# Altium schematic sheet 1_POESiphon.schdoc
size 309 x 223 mm; Symbol: Sheet-Symbol_A4; Device: Sheet-Symbol_A4; @Project Name: ODrive Rev Motor Module; @Page Count: 5; @Update Date: 2024-10-22; @Create Date: 2024-10-18; @Schematic Name: Schematic-A; @Page No: 1; @Page Name: POESiphon; Company: EasyEDA.com; Reviewed: EasyEDA; Version: V0.1; Page Size: A4; Part Number: JLCPCB-002; Drawn: EasyEDA; @Board Name: BaseModule; @Create Time: 18:23:50; @Update Time: 18:48:05
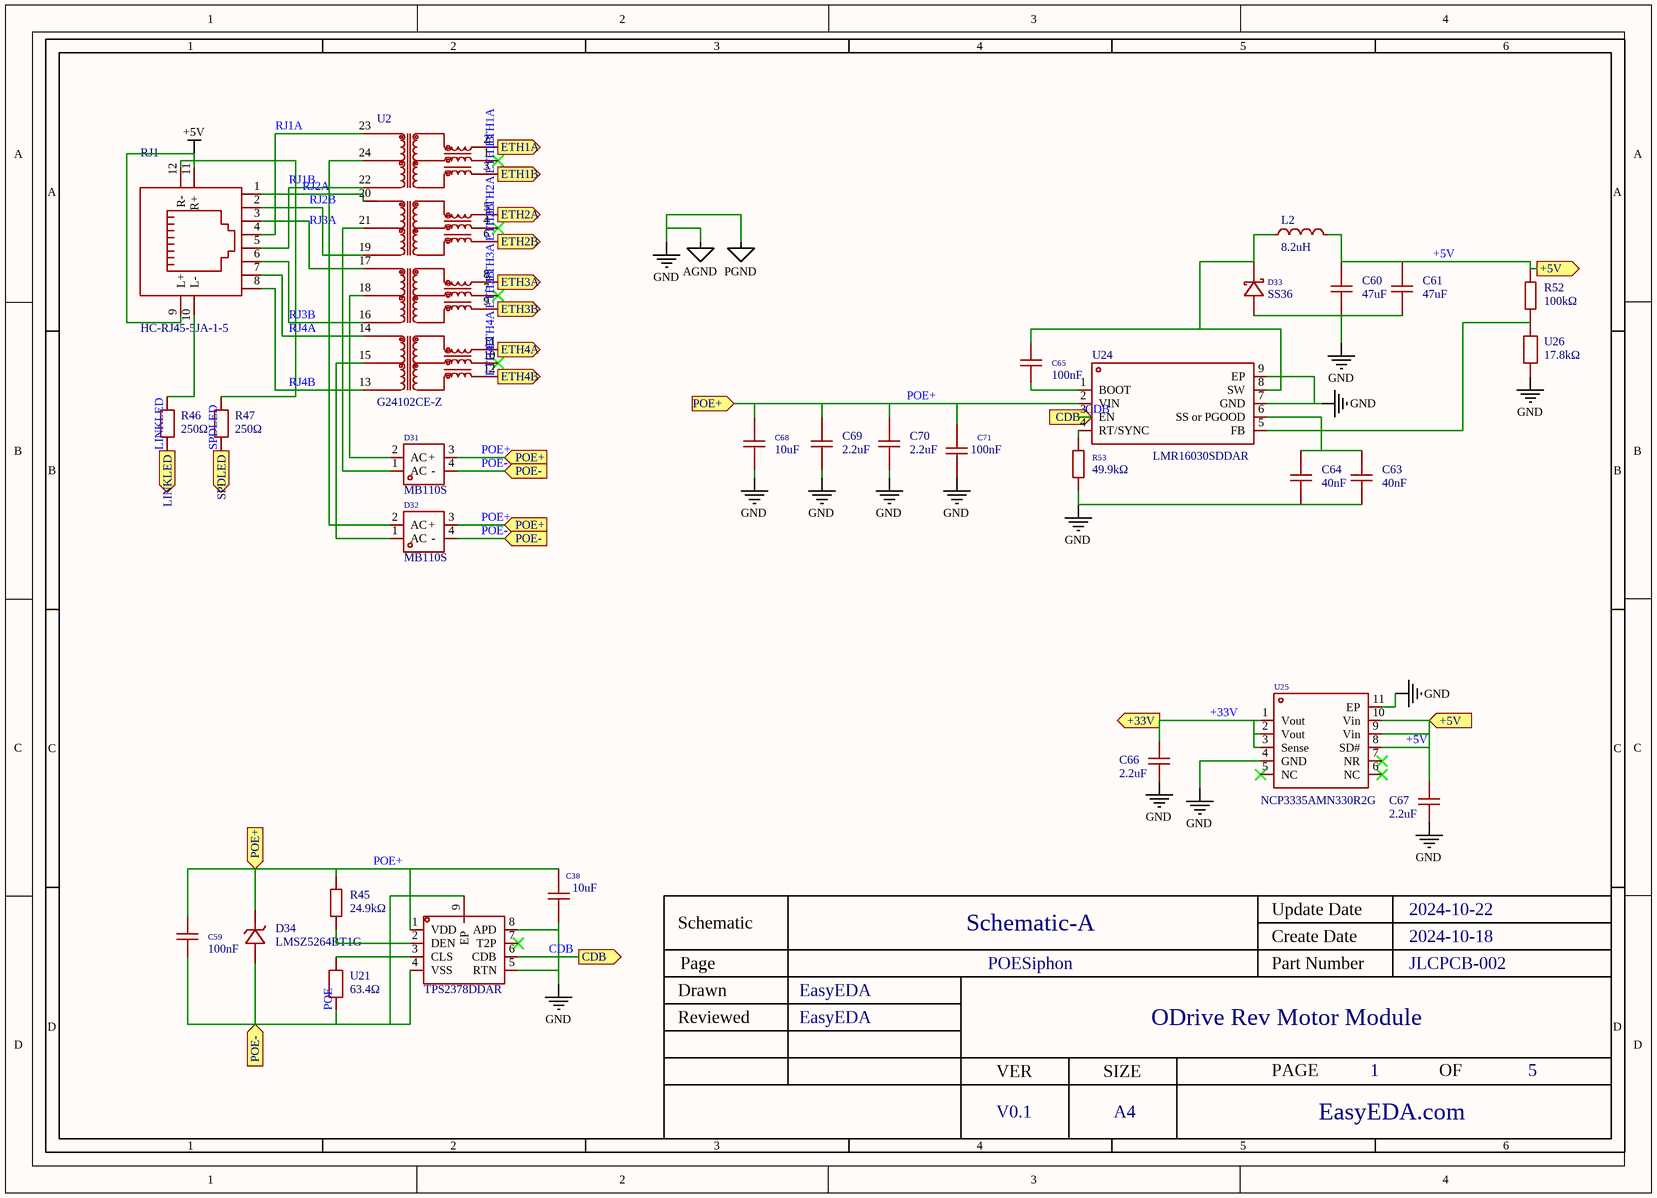
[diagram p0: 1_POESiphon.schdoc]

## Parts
C38  10uF  [C2220]  (value not drawn)
C59  100nF  [C0805]  (value not drawn)
C60  47uF  [C1210]  (value not drawn)
C61  47uF  [C1210]  (value not drawn)
C63  40nF  [C0805]  (value not drawn)
C64  40nF  [C0805]  (value not drawn)
C65  100nF  [C0805]  (value not drawn)
C66  2.2uF  [C0603]  (value not drawn)
C67  2.2uF  [C0603]  (value not drawn)
C68  10uF  [C1210]  (value not drawn)
C69  2.2uF  [C1206]  (value not drawn)
C70  2.2uF  [C1206]  (value not drawn)
C71  100nF  [C0603]  (value not drawn)
D31  MB110S  [MBS_L4.7-W4.0-P2.50-LS7.0-BL]  (value not drawn)
D32  MB110S  [MBS_L4.7-W4.0-P2.50-LS7.0-BL]  (value not drawn)
D33  SS36  [SMA_L4.4-W2.6-LS5.0-RD]  (value not drawn)
D34  LMSZ5264BT1G  [SOD-123_L2.7-W1.6-LS3.7-RD-1]  (value not drawn)
L2  8.2uH  [IND-SMD_L7.0-W6.6_FXL0630]  (value not drawn)
R45  24.9kΩ  [R0603]  (value not drawn)
R46  250Ω  [R0805]  (value not drawn)
R47  250Ω  [R0805]  (value not drawn)
R52  100kΩ  [R0402]  (value not drawn)
R53  49.9kΩ  [R0603]  (value not drawn)
RJ1  HC-RJ45-5JA-1-5  [RJ45-TH_HC-RJ45-5JA-1-5]  (value not drawn)
U2  G24102CE-Z  [SMD-24_L18.2-W12.2-P1.27_G24102CE-Z]  (value not drawn)
U17  TPS2378DDAR  [SO-8_L4.9-W3.9-P1.27-LS6.0-BL-EP]  (value not drawn)
U21  63.4Ω  [R0805]  (value not drawn)
U24  LMR16030SDDAR  [SO-8_L4.9-W3.9-P1.27-LS6.0-BL-EP]  (value not drawn)
U25  NCP3335AMN330R2G  [DFN-10_L3.0-W3.0-P0.50-BL-EP-1]  (value not drawn)
U26  17.8kΩ  [R0603]  (value not drawn)

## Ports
+5V (in), +5V (out), +33V (out), CDB (in), CDB (out), ETH1A (out), ETH1B (out), ETH2A (out), ETH2B (out), ETH3A (out), ETH3B (out), ETH4A (out), ETH4B (out), LINKLED (out), POE+ (in), POE- (in), SPDLED (out)

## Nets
+5V: C60.2 C61.2 C67.2 L2.2 R52.2 RJ1.9(L+) RJ1.11(R+) U25.8(SD#) U25.9(Vin) U25.10(Vin) ; port +5V
AGND: C38.1 C60.1 C61.1 C63.1 C64.1 C66.1 C67.1 C68.1 C69.1 C70.1 C71.1 D33.2(A) R53.1 U17.5(RTN) U17.8(APD) U24.7(GND) U24.9(EP) U25.4(GND) U25.11(EP) U26.1  [also labelled GND, PGND]
+33V: C66.2 U25.1(Vout) U25.2(Vout) U25.3(Sense) ; port +33V
CDB: U17.6(CDB) U24.3(EN) ; port CDB
ETH1A: U2.2 ; port ETH1A
ETH1B: U2.3 ; port ETH1B
ETH2A: U2.5 ; port ETH2A
ETH2B: U2.6 ; port ETH2B
ETH3A: U2.8 ; port ETH3A
ETH3B: U2.9 ; port ETH3B
ETH4A: U2.11 ; port ETH4A
ETH4B: U2.12 ; port ETH4B
LINKLED: R46.2 ; port LINKLED
POE+: C38.2 C59.1 C68.2 C69.2 C70.2 C71.2 D31.3(+) D32.3(+) D34.1(C) R45.2 U17.1(VDD) U24.2(VIN) ; port POE+
POE-: C59.2 D31.4(-) D32.4(-) D34.2(A) U17.4(VSS) U17.9(EP) U21.1 ; port POE-
RJ1A: RJ1.4 U2.23
RJ1B: RJ1.5 U2.22
RJ2A: RJ1.1 U2.20
RJ2B: RJ1.2 U2.19
RJ3A: RJ1.3 U2.17
RJ3B: RJ1.6 U2.16
RJ4A: RJ1.7 U2.14
RJ4B: RJ1.8 U2.13
SPDLED: R47.2 ; port SPDLED
NetC63_2: C63.2 C64.2 U24.6(SS_or_PGOOD)
NetC65_1: C65.1 D33.1(K) L2.1 U24.8(SW)
NetC65_2: C65.2 U24.1(BOOT)
NetD31_1: D31.1(AC) U2.21
NetD31_2: D31.2(AC) U2.18
NetD32_1: D32.1(AC) U2.15
NetD32_2: D32.2(AC) U2.24
NetR45_1: R45.1 U17.2(DEN)
NetR46_1: R46.1 RJ1.10(L-)
NetR47_1: R47.1 RJ1.12(R-)
NetR52_1: R52.1 U24.5(FB) U26.2
NetR53_2: R53.2 U24.4(RT/SYNC)
NetU17_3: U17.3(CLS) U21.2

Not connected (* = marked no-connect by the designer): U2 1* 4* 7* 10*; U17 7(T2P)*; U25 5(NC)* 6(NC)* 7(NR)*

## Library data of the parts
C38 = FS55X106K101EHG: Capacitance: Tolerance:±10% Tolerance:±10% Voltage Rated: Temperature Coefficient:; Manufacturer: PSA(信昌电陶); Add into BOM: yes; Tolerance: ±10%
C59 C65 = 0805B104K500NT: Capacitance:100nF Tolerance:±10% Tolerance:±10% Voltage Rated: Temperature Coefficient:; Manufacturer: FH(风华); Add into BOM: yes; Tolerance: ±10%
C60 C61 = CS3225X7R476K160NRL: Capacitance: Tolerance:±10% Tolerance:±10% Voltage Rated: Temperature Coefficient:; Manufacturer: SAMWHA(三和); Add into BOM: yes; Tolerance: ±10%
C63 C64 = 0805F403M500NT: Capacitance:40nF Tolerance:±20% Tolerance:±20% Voltage Rated: Temperature Coefficient:; Manufacturer: FH(风华); Add into BOM: yes; Tolerance: ±20%
C66 C67 = CL10A225KO8NNNC: Capacitance: Tolerance:±10% Tolerance:±10% Voltage Rated: Temperature Coefficient:; Manufacturer: SAMSUNG(三星); Add into BOM: yes; Tolerance: ±10%
C68 = FS32X106K101EGG: Capacitance: Tolerance:±10% Tolerance:±10% Voltage Rated: Temperature Coefficient:; Manufacturer: PSA(信昌电陶); Add into BOM: yes; Tolerance: ±10%
C69 C70 = CC1206KKX7R0BB225: Capacitance: Tolerance:±10% Tolerance:±10% Voltage Rated: Temperature Coefficient:; Manufacturer: YAGEO(国巨); Add into BOM: yes; Tolerance: ±10%
C71 = CC0603KRX7R0BB104: Capacitance: Tolerance:±10% Tolerance:±10% Voltage Rated: Temperature Coefficient:; Manufacturer: YAGEO(国巨); Add into BOM: yes; Tolerance: ±10%
D31 D32 = MB110S_C382811: Forward Voltage (Vf@If):850mV@1A Reverse Voltage (Vr): Average Rectified Current (Io): Reverse Leakage Current (Ir):200uA@100V Peak Forward Surge Current: Operating Temperature:-55℃~+125℃@(Tj) Operating Temperature:-55℃~+125℃@(Tj); Manufacturer: 晶导微电子; Add into BOM: yes
D33 = SS36_C727061: Diode Configuration:Single Forward Voltage (Vf@If):700mV@3A Reverse Voltage (Vr):60V Average Rectified Current (Io):3A Reverse Leakage Current (Ir):500uA@60V; Manufacturer: TWGMC(台湾迪嘉); Add into BOM: yes; Diode Configuration: Single; Reverse Voltage (Vr): 60V; Average Rectified Current (Io): 3A
D34 = LMSZ5264BT1G: Diode Configuration:Single Zener Voltage (Nom):60V Reverse Leakage Current (Ir):2.1mA Zener Voltage (Range):57V~63V Zener Voltage (Range):57V~63V Power Dissipation:500mW Zener Impedance (Zzt):170Ω Tolerance:±5% Tolerance:±5%; Manufacturer: LRC(乐山无线电); Add into BOM: yes; Diode Configuration: Single; Zener Voltage (Nom): 60V; Reverse Leakage Current (Ir): 2.1mA; Power Dissipation: 500mW; Zener Impedance (Zzt): 170Ω; Tolerance: ±5%
L2 = FXL0630-8R2-M: Inductance: Tolerance:±20% Tolerance:±20% Rated Current: Saturation Current (Isat):6A DC Resistance (DCR): Type:Integrated molded inductor; Manufacturer: cjiang(长江微电); Add into BOM: yes; Tolerance: ±20%; Saturation Current (Isat): 6A
R45 = 0603WAF2492T5E: Type:Thick Film Resistors Resistance:24.9kΩ Tolerance:±1% Tolerance:±1% Power(Watts): Overload Voltage (Max): Temperature Coefficient:±100ppm/℃ Temperature Coefficient:±100ppm/℃ Operating Temperature Range:-55℃~+155℃ Operating Temperature Range:-55℃~+155℃; Manufacturer: UNI-ROYAL(厚声); Add into BOM: yes; Tolerance: ±1%
R46 R47 = ARG05DTC2500N: Type:Thin Film Resistor Resistance: Tolerance:±0.5% Tolerance:±0.5% Power(Watts): Overload Voltage (Max): Temperature Coefficient:±25ppm/℃ Temperature Coefficient:±25ppm/℃ Operating Temperature Range:-55℃~+155℃ Operating Temperature Range:-55℃~+155℃; Manufacturer: Viking(光颉); Add into BOM: yes; Tolerance: ±0.5%
R52 = RC0402FR-07100KL: Type:Thick Film Resistors Resistance: Tolerance:±1% Tolerance:±1% Power(Watts): Overload Voltage (Max): Temperature Coefficient:±100ppm/℃ Temperature Coefficient:±100ppm/℃ Operating Temperature Range:-55℃~+155℃ Operating Temperature Range:-55℃~+155℃; Manufacturer: YAGEO(国巨); Add into BOM: yes; Tolerance: ±1%
R53 = 0603WAF4992T5E: Type:Thick Film Resistors Resistance:49.9kΩ Tolerance:±1% Tolerance:±1% Power(Watts): Overload Voltage (Max): Temperature Coefficient:±100ppm/℃ Temperature Coefficient:±100ppm/℃ Operating Temperature Range:-55℃~+155℃ Operating Temperature Range:-55℃~+155℃; Manufacturer: UNI-ROYAL(厚声); Add into BOM: yes; Tolerance: ±1%
RJ1 = HC-RJ45-5JA-1-5: Connector Type:RJ45Receptacle Number of Ports:1 Mounting Style:Right-Angle Shielding:Unshielded LED:WithLED Contact Material:Phosphor coppe Contact Plating:Gold Soldering Temperature(Max):260℃@3S; Manufacturer: HCTL(华灿天禄); Add into BOM: yes; Number of Ports: 1
U2 = G24102CE-Z: Manufacturer: Mentech(铭普光磁); Add into BOM: yes
U17 = TPS2378DDAR: Application Function: Number of Channels: Interface:; Manufacturer: TI(德州仪器); Add into BOM: yes
U21 = CR0805F863R4G: Resistance: Tolerance:±1% Tolerance:±1% Power(Watts): Overload Voltage (Max): Temperature Coefficient:- Temperature Coefficient:- Operating Temperature Range:- Operating Temperature Range:-; Manufacturer: LIZ(丽智电子); Add into BOM: yes; Tolerance: ±1%
U24 = LMR16030SDDAR: Function:Step-down type Output Type:Adjustable Input Voltage:4.3V~60V Input Voltage:4.3V~60V Output Voltage:800mV~50V Output Voltage:800mV~50V Output Current (Max):3A Switching Frequency:2.5MHz Operating Temperature:-40℃~+125℃@(TJ) Operating Temperature:-; Manufacturer: TI(德州仪器); Add into BOM: yes; Output Current (Max): 3A; Switching Frequency: 2.5MHz; Synchronous Rectification: NO; Number of Outputs: 1; Switch tube (built-in/external): 内置
U25 = NCP3335AMN330R2G: Output Type:固定 Maximum Input Voltage:16V Output Voltage:3.3V Output Voltage:3.3V MAX Output Current:500mA Dropout Voltage:0.34V@(500mA) standby current:190uA Operating Temperature:-40℃~+85℃ Operating Temperature:-40℃~+85℃ Output Polarity:Positive electrod; Manufacturer: onsemi(安森美); Add into BOM: yes; Output Type: 固定; Maximum Input Voltage: 16V; Output Voltage: 3.3V; standby current: 190uA; Output Polarity: Positive electrode; Number of Outputs: 1
U26 = FRC0603F1782TS: Type:Thick Film Resistors Resistance:17.8kΩ Tolerance:±1% Tolerance:±1% Power(Watts): Overload Voltage (Max): Temperature Coefficient:±100ppm/℃ Temperature Coefficient:±100ppm/℃ Operating Temperature Range:-55℃~+155℃ Operating Temperature Range:-55℃~+155℃; Manufacturer: FOJAN(富捷); Add into BOM: yes; Tolerance: ±1%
